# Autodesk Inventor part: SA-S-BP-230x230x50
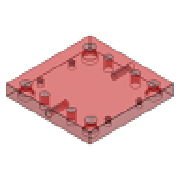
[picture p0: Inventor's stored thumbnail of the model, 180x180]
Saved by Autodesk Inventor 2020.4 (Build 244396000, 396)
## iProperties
Created: 2019-01
Part Number: SA-S-BP-230x230x50
Material: S 55 C
Description: Core Plate
Document SubType Name: Modeling
Designer: mel
Standard Revision: 1
Manufacturer: FUTABA
Language: fr-FR
Size Designation: 230x230x50
Categories: <MemberInstance><Categories><Category DisplayName="Moule" InternalName="349578f2-f4d4-4954-8c09-8e99297a61c0" Mnemonic="MOLD"><Category DisplayName="Plaque de m
Density: 7.85 g/cm^3
Appearance: Dark Red
IsCustomPart: 1
Author: mel
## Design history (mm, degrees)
sketch "Sketch1"
  geometry: L1 (-115, 115)-(115, 115); L2 (115, 115)-(115, -115); L3 (115, -115)-(-115, -115); L4 (-115, -115)-(-115, 115); 7 further points
  constraints: 8 end point, 2 horizontal alignment, 2 midpoint, 2 parallel, 1 horizontal, 1 perpendicular, 1 vertical alignment
  dimensions: "d123" = 230 distance between parallel lines of L2 L4 (= W_); "d124" = 230 distance between parallel lines of L3 L1 (= L); "d125" = 90 vertical distance of point (0, 0) point (-53, 90) (= 0.5 x RP_L); "d126" = 53 horizontal distance of point (0, 0) point (-53, 90) (= 0.5 x RP_W); "d127" = 92 horizontal distance of point (0, 0) point (-92, 92) (= 0.5 x GP_W); "d128" = 92 horizontal distance of point (0, 0) point (-92, 92) (= 0.5 x GP_L); "d129" = 92.5 horizontal distance of point (0, 0) point (-92.5, 53) (= 0.5 x S1_W); "d130" = 53 vertical distance of point (0, 0) point (-92.5, 53) (= 0.5 x S1_L); "d140" = 92 horizontal distance of point (92, 92) point (0, 0) (= 0.5 x GP_W)
extrude "Extrusion1" new body sketch "Sketch1" distance "d20" = 50 (= H_); taper "d30" = 0 deg
sketch "Sketch2"
  geometry: L1 (230, 0)-(0, 0) reference; 3 further points
  constraints: 1 midpoint, 1 vertical alignment
  dimensions: "d186" = 25 distance from line of L1 point (115, 25) (= 0.5 x H_)
hole "Hole1" sketch "Sketch2" at (115, 25) diameter "d104" = 13.835; stored, may be unused: countersink angle "d108" = 90 deg, drill point angle "d110" = 118 deg; dims "d105" = 29 (= le), "d106" = 26 (= GP_d2), "d107" = 6 (= GP_k), "d109" = 39 (= ke)
sketch "Sketch3"
  geometry: L1 (0, 0)-(230, 0) reference; 3 further points
  constraints: 1 midpoint, 1 vertical alignment
  dimensions: "d187" = 25 distance from line of point (115, -25) L1 (= 0.5 x H_)
hole "Hole2" sketch "Sketch3" at (115, -25) diameter "d113" = 13.835; stored, may be unused: countersink angle "d117" = 90 deg, drill point angle "d119" = 118 deg; dims "d114" = 29 (= le), "d115" = 26 (= GP_d2), "d116" = 6 (= GP_k), "d118" = 39 (= ke)
hole "Hole3" sketch "Sketch1" diameter "d131" = 10.106; stored, may be unused: countersink angle "d135" = 90 deg, drill point angle "d137" = 118 deg; dims "d132" = 15 (= H_l), "d133" = 4, "d134" = 2, "d136" = 24 (= H_u)
pattern_linear "Rectangular Pattern1" dims "d164" = 106 (computed from S1_L, Ns), "d167" = 185 (computed from S1_W, Nw)
hole "Hole4" sketch "Sketch1" diameter "d141" = 20 (= GP_d1); stored, may be unused: countersink angle "d145" = 90 deg, drill point angle "d147" = 0 deg; dims "d142" = 6, "d143" = 26 (= GP_d2), "d144" = 6 (= GP_k), "d146" = 50 (= H_)
pattern_linear "Rectangular Pattern2" dims "d170" = 184 (computed from GP_L, Nl)
hole "Hole5" sketch "Sketch1" diameter "d148" = 20 (= GP_d1); stored, may be unused: countersink angle "d152" = 90 deg, drill point angle "d154" = 0 deg; dims "d149" = 6, "d150" = 26 (= GP_d2), "d151" = 6 (= GP_k), "d153" = 50 (= H_)
pattern_linear "Rectangular Pattern3" dims "d173" = 182 (computed from GP_L2, GP_L1, Nl)
hole "Hole6" sketch "Sketch1" diameter "d155" = 15 (= RP_dt); stored, may be unused: countersink angle "d159" = 90 deg, drill point angle "d161" = 0 deg; dims "d156" = 6, "d157" = 26 (= GP_d2), "d158" = 6 (= GP_k), "d160" = 50 (= H_)
pattern_linear "Rectangular Pattern4" dims "d176" = 180 (computed from RP_L, Nl), "d179" = 106 (computed from RP_W, Nw)
chamfer "Chamfer1" distance "d180" = 0.5; stored, may be unused: second distance "d181" = 2, angle "d182" = 45 deg
feature "Sculpter1"
body "Solid1"
feature "Surface1"
body "Srf1"
other parameters: "L" = 230 [user parameter; used in 1 equation term], "W_" = 230 [user parameter; used in 3 equation terms], "H_" = 50 [user parameter; used in 8 equation terms], "GP_W" = 184 [user parameter; used in 2 equation terms], "GP_d1" = 20 [user parameter; used in 2 equation terms], "GP_d2" = 26 [user parameter; used in 5 equation terms], "GP_k" = 6 [user parameter; used in 5 equation terms], "S1_L" = 106 [user parameter; used in 2 equation terms], "S1_W" = 185 [user parameter; used in 2 equation terms], "GP_L1" = 92 [user parameter; used in 1 equation term], "RP_W" = 106 [user parameter; used in 2 equation terms], "RP_dt" = 15 [user parameter; used in 1 equation term], "GP_L" = 184 [user parameter; used in 2 equation terms], "d102" = 25 (= 0.5 x H_), "d103" = 115 (= 0.5 x W_), "d111" = 115 (= 0.5 x W_), "d112" = 25 (= 0.5 x H_), "le" = 29 [user parameter; used in 2 equation terms], "ke" = 39 [user parameter; used in 2 equation terms], "H_l" = 15 [user parameter; used in 1 equation term], "H_u" = 24 [user parameter; used in 1 equation term]
